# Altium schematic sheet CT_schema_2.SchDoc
size 322 x 309 mm
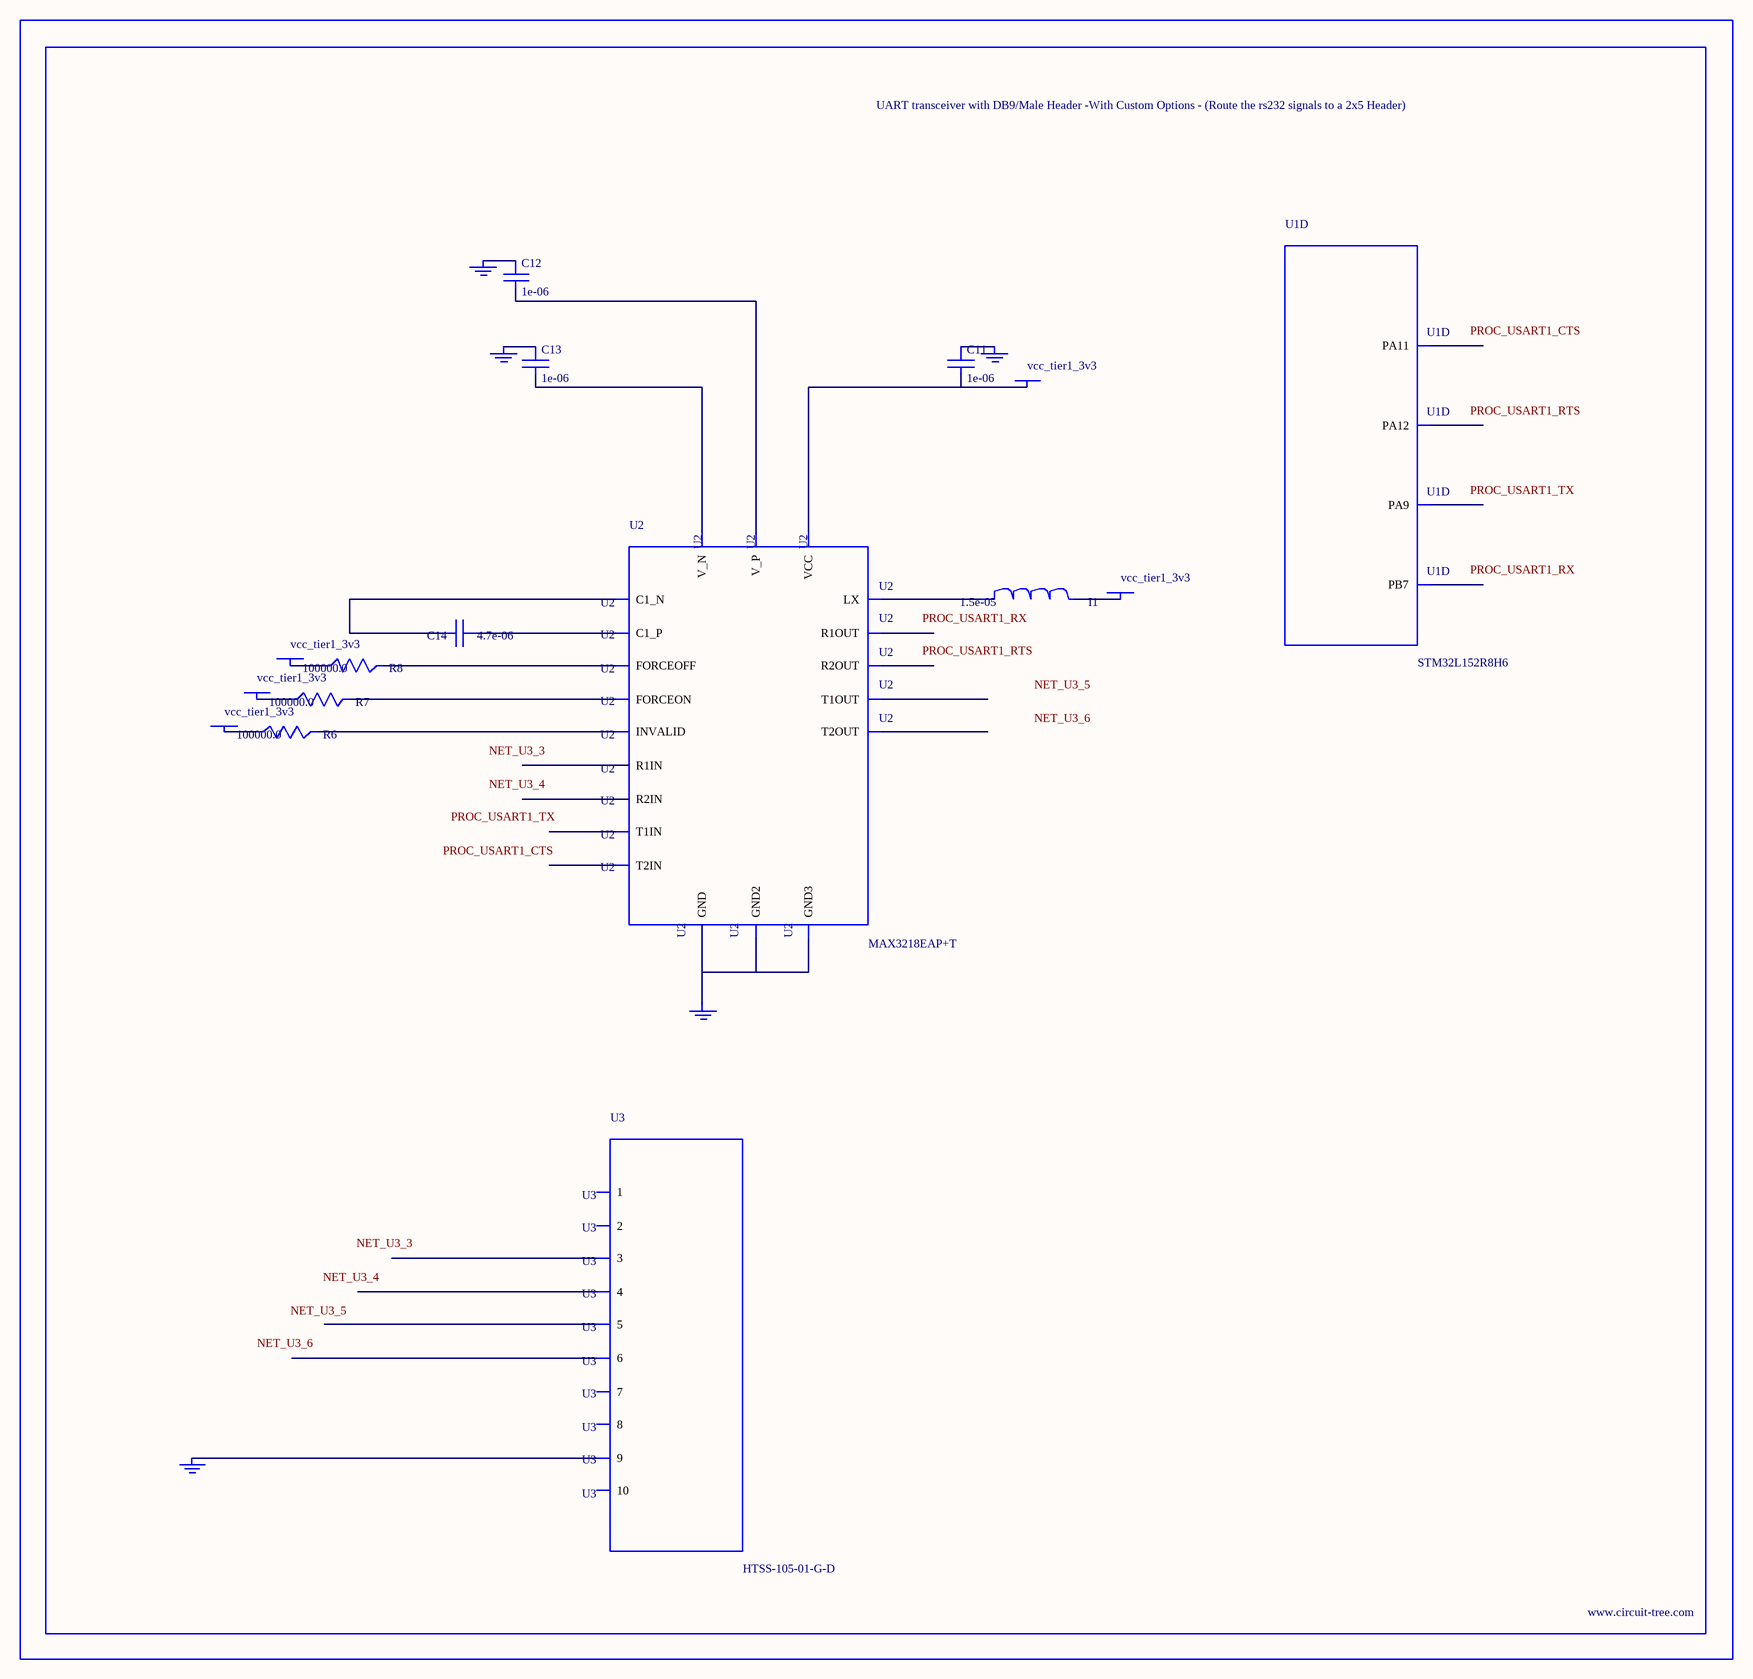
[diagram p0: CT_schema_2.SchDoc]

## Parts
BORDER1  (no value)
C11  1e-06  [C0603]
C12  1e-06  [C0603]
C13  1e-06  [C0603]
C14  4.7e-06  [C0805]
GND_INSTANCE_1_0  (no value)
GND_INSTANCE_1_1  (no value)
GND_INSTANCE_1_2  (no value)
GND_INSTANCE_1_3  (no value)
GND_INSTANCE_1_4  (no value)
I1  1.5e-05  [L1210]
POWER_INSTANCE_1_0  vcc_tier1_3v3
POWER_INSTANCE_1_1  vcc_tier1_3v3
POWER_INSTANCE_1_2  vcc_tier1_3v3
POWER_INSTANCE_1_3  vcc_tier1_3v3
POWER_INSTANCE_1_4  vcc_tier1_3v3
R6  100000.0  [R0603]
R7  100000.0  [R0603]
R8  100000.0  [R0603]
U1  STM32L152R8H6  [TFBGA64]  (part D of 6)
U2  MAX3218EAP+T  [SSOP-20]
U3  HTSS-105-01-G-D  [HTSS-105-01-G-D]

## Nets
NetC11_1: C11.1 GND_INSTANCE_1_0.0(GND)
NetC11_2: C11.2 POWER_INSTANCE_1_4.0(PWR) U2.6(VCC)
NetC12_1: C12.1 GND_INSTANCE_1_2.0(GND)
NetC12_2: C12.2 U2.19(V_P)
NetC13_1: C13.1 GND_INSTANCE_1_1.0(GND)
NetC13_2: C13.2 U2.15(V_N)
NetC14_1: C14.1 U2.18(C1_P)
NetC14_2: C14.2 U2.16(C1_N)
NetGND_INSTANCE_1_3_0: GND_INSTANCE_1_3.0(GND) U2.5(GND) U2.17(GND2) U2.20(GND3)
NetGND_INSTANCE_1_4_0: GND_INSTANCE_1_4.0(GND) U3.9
NetI1_1: I1.1 U2.1(LX)
NetI1_2: I1.2 POWER_INSTANCE_1_0.0(PWR)
NetPOWER_INSTANCE_1_1_0: POWER_INSTANCE_1_1.0(PWR) R6.1
NetPOWER_INSTANCE_1_2_0: POWER_INSTANCE_1_2.0(PWR) R7.1
NetPOWER_INSTANCE_1_3_0: POWER_INSTANCE_1_3.0(PWR) R8.1
NetR6_2: R6.2 U2.2(INVALID)
NetR7_2: R7.2 U2.3(FORCEON)
NetR8_2: R8.2 U2.4(FORCEOFF)

Not connected (* = marked no-connect by the designer): U1 B8(PA12) C3(PB7) C7(PA9) C8(PA11); U2 7(T1IN) 8(T2IN) 9(R1OUT) 10(R2OUT) 11(R2IN) 12(R1IN) 13(T2OUT) 14(T1OUT); U3 1 2 3 4 5 6 7 8 10

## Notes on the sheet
- Labels drawn without touching a wire or pin: NET_U3_3, NET_U3_4, NET_U3_5, NET_U3_6, PROC_USART1_CTS, PROC_USART1_RTS, PROC_USART1_RX, PROC_USART1_TX

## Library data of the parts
BORDER1 = BORDER_PAGE1
C11-C13 = C0603C105K3RACTU
C14 = C0805C475K4RACTU
GND_INSTANCE_1_0-GND_INSTANCE_1_4 = GND
I1 = L1210R150MDWIT
POWER_INSTANCE_1_0-POWER_INSTANCE_1_4 = PWR
R6-R8 = RC0603JR-07100KL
